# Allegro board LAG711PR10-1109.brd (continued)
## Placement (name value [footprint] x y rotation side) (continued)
RB9  0_0201_5%  [R_0201]  184.1 32.19 180 top
RB10  0_0201_5%  [R_0201]  55.53 26.27 90 top
RB11  0_0201_5%  [R_0201]  169.33 57.26 90 top
RB12  0_0201_5%  [R_0201]  169.33 58.17 270 bottom
RC1  1K_0402_5%  [R_0402]  142.1 81.34 180 bottom
RC2  1K_0402_5%  [R_0402]  139.68 64.07 180 bottom
RC3  49.9_0402_1%  [R_0402]  140.32 80.45 180 bottom
RC4  24.9_0402_1%  [R_0402]  131.49 74.76 180 top
RC5  10K_0402_5%  [R_0402]  109.05 53.27 0 bottom
RC6  10K_0402_5%  [R_0402]  108.67 50.73 0 bottom
RC7  2.2K_0402_5%  [R_0402]  145.27 53.91 180 top
RC8  2.2K_0402_5%  [R_0402]  145.27 53.14 180 top
RC9  2.2K_0402_5%  [R_0402]  140.57 51.37 180 bottom
RC10  100K_0402_5%  [R_0402]  99.83 50.99 180 top
RC11  100K_0402_5%  [R_0402]  131.61 106.1 0 bottom
RC12  100K_0402_5%  [R_0402]  143.75 42.98 180 bottom
RC13  100K_0402_5%  [R_0402]  130.84 51.32 270 top
RC14  0_0201_5%  [R_0201]  108.96 49.97 0 bottom
RC15  49.9_0402_1%  [R_0402]  120.55 59.33 270 top
RC16  49.9_0402_1%  [R_0402]  120.55 56.34 270 top
RC17  121_0402_1%  [R_0402]  119.43 61.91 180 top
RC18  80.6_0402_1%  [R_0402]  120.14 61.91 0 top
RC19  200K_0402_1%  [R_0402]  107.86 110.37 270 top
RC20  100_0402_1%  [R_0402]  117.55 61.81 180 top
RC21  0_0402_5%  [R_0402]  112.81 32.49 90 bottom
RC22  0_0402_5%  [R_0402]  110.52 33.13 90 bottom
RC23  0_0402_5%  [R_0402]  109 33.13 90 bottom
RC24  0_0402_5%  [R_0402]  114.33 33.13 90 bottom
RC25  0_0402_5%  [R_0402]  112.05 33.13 90 bottom
RC26  33_0402_5%  [R_0402]  105.9 53.14 180 top
RC27  10K_0402_5%  [R_0402]  121.07 43.92 90 bottom
RC28  2.2K_0402_5%  [R_0402]  129.19 40.32 90 bottom
RC29  2.2K_0402_5%  [R_0402]  125.13 40.39 270 bottom
RC30  0_0603_5%  [R0603_0OHM]  119.1 39.75 270 bottom
RC31  4.7K_0402_5%  [R_0402]  131.56 37.27 180 bottom
RC32  1K_0402_1%  [R_0402]  108.24 34.04 270 bottom
RC33  1K_0402_5%  [R_0402]  127.16 43.67 90 top
RC34  1K_0402_5%  [R_0402]  127.92 43.67 90 top
RC35  100K_0402_5%  [R_0402]  109.76 33.13 90 bottom
RC36  100K_0402_5%  [R_0402]  115.1 33.13 90 bottom
RC37  100K_0402_5%  [R_0402]  111.29 33.13 90 bottom
RC38  4.7K_0402_5%  [R_0402]  125.76 45.32 90 top
RC39  49.9_0402_1%  [R_0402]  114.72 31.76 270 bottom
RC40  49.9_0402_1%  [R_0402]  113.19 30.84 90 bottom
RC41  49.9_0402_1%  [R_0402]  111.67 31.76 270 bottom
RC42  49.9_0402_1%  [R_0402]  108.37 30.91 90 top
RC43  49.9_0402_1%  [R_0402]  112.18 30.91 90 top
RC44  4.7K_0402_5%  [R_0402]  125 45.32 90 top
RC45  33_0402_5%  [R_0402]  118.19 35.17 0 bottom
RC46  4.7K_0402_5%  [R_0402]  116.49 53.07 90 top
RC47  33_0402_5%  [R_0402]  110.7 62.92 0 bottom
RC48  33_0402_5%  [R_0402]  108.54 60.71 0 bottom
RC49  33_0402_5%  [R_0402]  108.54 62.23 0 bottom
RC50  1K_0402_5%  [R_0402]  110.7 62.16 0 bottom
RC51  4.7K_0402_5%  [R_0402]  108.54 61.47 0 bottom
RC52  10K_0402_5%  [R_0402]  122.72 42.43 270 bottom
RC53  10K_0402_5%  [R_0402]  124.88 43.42 90 top
RC54  200_0402_1%  [R_0402]  116.49 52.21 270 top
RC55  10K_0402_5%  [R_0402]  123.48 41.51 90 bottom
RC56  10K_0402_5%  [R_0402]  125.64 44.33 270 top
RC57  4.7K_0402_5%  [R_0402]  108.67 49.21 0 bottom
RC58  100K_0402_5%  [R_0402]  110.83 57.84 0 bottom
RC59  10K_0402_5%  [R_0402]  119.95 43.92 90 bottom
RC60  150_0201_1%  [R_0201]  117.41 46.45 180 top
RC61  10K_0402_5%  [R_0402]  125.57 52.87 0 top
RC62  4.7K_0402_5%  [R_0402]  119.67 43.92 90 top
RC63  10K_0402_5%  [R_0402]  119.55 42.48 180 bottom
RC64  200_0402_1%  [R_0402]  125.94 48.83 0 top
RC65  4.7K_0402_5%  [R_0402]  119.19 43.92 90 bottom
RC66  10K_0402_5%  [R_0402]  110.83 58.61 0 bottom
RC68  10K_0402_5%  [R_0402]  89.58 117.41 180 top
RC69  10K_0402_5%  [R_0402]  127.16 46.34 90 top
RC70  10K_0402_5%  [R_0402]  130.72 48.62 90 top
RC71  10K_0402_5%  [R_0402]  127.87 48.06 180 top
RC72  10K_0402_5%  [R_0402]  129.96 49.54 270 top
RC73  71.5K_0402_1%  [R_0402]  119.82 50.97 180 top
RC74  75K_0402_1%  [R_0402]  117.26 52.21 270 top
RC75  10K_0402_5%  [R_0402]  96.1 56.07 0 top
RC76  1K_0402_5%  [R_0402]  140.7 71.18 180 bottom
RC77  20K_0402_5%  [R_0402]  103.36 57.4 180 top
RC78  10K_0402_5%  [R_0402]  125.45 116.7 90 bottom
RC79  0_0201_5%  [R_0201]  105.9 56.26 180 top
RC80  0_0201_5%  [R_0201]  105.9 55.49 180 top
RC81  10K_0402_5%  [R_0402]  72.17 136.25 90 top
RC82  20K_0402_5%  [R_0402]  104.99 57.4 0 top
RC83  60.4_0402_1%  [R_0402]  139.66 50.6 0 bottom
RC84  0_0201_5%  [R_0201]  140.84 45.91 0 bottom
RC85  10K_0402_5%  [R_0402]  31.4 81.54 270 top
RC86  10K_0402_5%  [R_0402]  140.8 45.14 0 bottom
RC87  1M_0402_5%  [R_0402]  108.54 59.95 0 bottom
RC88  10K_0402_5%  [R_0402]  29.12 30.11 270 top
RC89  33_0402_5%  [R_0402]  140.17 47.18 0 bottom
RC90  200K_0402_1%  [R_0402]  141.89 47.16 90 bottom
RC91  33_0402_5%  [R_0402]  140.17 48.06 0 bottom
RC92  4.7K_0402_5%  [R_0402]  104.99 54.73 0 top
RC93  10K_0402_5%  [R_0402]  110.83 56.32 0 bottom
RC94  100K_0402_5%  [R_0402]  94.33 54.68 270 top
RC95  10M_0402_5%  [R_0402]  104.16 47.11 0 top
RC96  10K_0402_5%  [R_0402]  110.83 57.08 0 bottom
RC97  10K_0402_5%  [R_0402]  108.54 58.61 0 bottom
RC98  100K_0402_5%  [R_0402]  109.46 57.08 180 bottom
RC99  62_0402_1%  [R_0402]  139.68 64.83 180 bottom
RC100  10K_0402_5%  [R_0402]  131.15 43.8 90 bottom
RC101  0_0201_5%  [R0201_0OHM]  104.99 61.46 0 top
RC102  0_0201_5%  [R0201_0OHM]  104.99 53.97 0 top
RC103  4.7K_0402_5%  [R_0402]  102.45 60.57 0 top
RC104  4.7K_0402_5%  [R_0402]  105.9 60.51 180 top
RC105  1M_0402_5%  [R_0402]  93.84 55.94 180 top
RC106  10K_0402_5%  [R_0402]  104.99 49.33 0 top
RC107  10K_0402_5%  [R_0402]  123.48 44.84 270 bottom
RC108  4.7K_0402_5%  [R_0402]  123.48 43.92 90 top
RC109  10K_0402_5%  [R_0402]  130.08 40.32 90 bottom
RC110  10K_0402_5%  [R_0402]  130.39 43.8 90 bottom
RC111  100K_0402_5%  [R_0402]  122.72 43.92 90 bottom
RC112  4.7K_0402_5%  [R_0402]  119.86 49.2 90 top
RC113  10K_0402_5%  [R_0402]  129.62 43.8 90 bottom
RC114  10K_0402_5%  [R_0402]  121.07 42.43 270 bottom
RC115  4.7K_0402_5%  [R_0402]  110.83 55.56 0 bottom
RC116  150K_0402_5%  [R_0402]  121 39.16 90 bottom
RC117  10K_0402_5%  [R_0402]  121.95 43.92 90 bottom
RC118  10K_0402_5%  [R_0402]  109.46 55.56 180 bottom
RC119  10K_0402_5%  [R_0402]  121.95 42.43 270 bottom
RC120  10K_0402_5%  [R_0402]  120.65 53.78 0 top
RC121  20K_0402_5%  [R_0402]  121.19 43.92 90 top
RC122  20K_0402_5%  [R_0402]  121.95 43.92 90 top
RC123  113_0402_1%  [R_0402]  144.36 54.8 0 top
RC124  0_0402_5%  [R_0402]  131.21 52.97 180 top
RC125  0_0402_5%  [R_0402]  144.36 55.56 0 top
RC126  100_0402_1%  [R_0402]  133.46 51.11 180 top
RC127  10K_0402_5%  [R_0402]  131.81 40.32 180 bottom
RC128  0_0603_5%  [R0603_0OHM]  129.96 59.18 270 top
RC129  0_0603_5%  [R_0603]  145.83 62.16 180 top
RC130  0_0603_5%  [R_0603]  144.37 41.71 180 bottom
RC131  0_0402_5%  [R0402_0OHM]  123.53 60.89 0 top
RC132  0_0402_5%  [R0402_0OHM]  122.5 57.08 90 top
RC133  0_0402_5%  [R_0402]  122.34 55.68 270 top
RC134  56_0402_5%  [R_0402]  142.22 78.54 180 bottom
RC135  220_0402_5%  [R_0402]  139.4 78.54 0 bottom
RC136  100_0402_1%  [R_0402]  140.32 79.56 180 bottom
RC137  1K_0402_1%  [R_0402]  142.74 83.22 180 bottom
RC138  1K_0402_1%  [R_0402]  142.74 83.98 180 bottom
RC139  49.9_0402_1%  [R_0402]  144.29 81.15 0 top
RC140  1K_0402_1%  [R_0402]  140.64 90.99 180 bottom
RC141  1K_0402_1%  [R_0402]  142.27 89.23 180 bottom
RC142  1K_0402_1%  [R_0402]  142.27 87.7 180 bottom
RC143  1K_0402_1%  [R_0402]  142.27 88.46 180 bottom
RC144  10K_0402_1%  [R_0402]  97.65 48.45 180 top
RC145  100K +-5% 0402  [R_0402]  140.5 63.99 90 bottom
RC146  10K_0402_5%  [R_0402]  94.27 46.36 270 top
RC147  0_0201_5%  [R0201_0OHM]  93.21 44.76 0 top
RC148  0_0201_5%  [R0201_0OHM]  93.8 44.13 180 top
RC149  1K_0402_5%  [R_0402]  107.48 33.13 90 bottom
RC150  51_0402_5%  [R_0402]  145.21 84.2 180 top
RC151  51_0402_5%  [R_0402]  145.21 83.43 180 top
RC152  100_0402_5%  [R_0402]  145.21 81.91 180 top
RC153  1.5K_0402_1%  [R_0402]  142.74 82.46 180 bottom
RC154  1.5K_0402_1%  [R_0402]  141.36 86.94 0 bottom
RC155  1K_0402_5%  [R_0402]  103.36 61.53 180 top
RC156  51_0402_5%  [R_0402]  144.29 84.96 0 top
RC157  51_0402_5%  [R_0402]  144.29 82.67 0 top
RC158  10K_0402_5%  [R_0402]  27.09 131.05 90 bottom
RC160  499_0402_1%  [R_0402]  140.32 81.34 180 bottom
RC162  20K_0402_5%  [R_0402]  122.72 43.92 90 top
RC164  100_0402_1%  [R_0402]  144.31 65.07 90 top
RC165  100_0402_1%  [R_0402]  144.31 66.72 90 top
RC167  100_0402_1%  [R_0402]  144.31 71.36 90 top
RC168  100_0402_1%  [R_0402]  144.31 73.01 90 top
RC169  100_0402_1%  [R_0402]  139.86 95.64 270 bottom
RC170  100_0402_1%  [R_0402]  139.86 93.92 270 bottom
RC171  0_0201_5%  [R_0201]  139.7 91.69 0 bottom
RC172  0_0201_5%  [R_0201]  116.49 92.43 270 top
RC173  0_0201_5%  [R_0201]  139.7 92.32 0 bottom
RC174  10K_0402_5%  [R_0402]  128.86 43.8 90 bottom
RC175  10K_0402_5%  [R_0402]  120.43 43.92 90 top
RC177  49.9_0402_1%  [R_0402]  114.21 31.89 270 top
RC178  49.9_0402_1%  [R_0402]  112.43 30.84 90 bottom
RC179  49.9_0402_1%  [R_0402]  111.41 30.91 90 top
RC180  49.9_0402_1%  [R_0402]  109.13 30.91 90 top
RC181  49.9_0402_1%  [R_0402]  110.91 31.76 270 bottom
RC182  4.7K_0402_5%  [R_0402]  117.78 48.69 270 top
RC183  4.7K_0402_5%  [R_0402]  118.54 48.69 270 top
RC187  100K_0402_5%  [R_0402]  113.57 33.13 90 bottom
RC188  10K_0402_5%  [R_0402]  131.48 49.54 270 top
RC189  10K_0402_5%  [R_0402]  133 49.54 270 top
RC190  10K_0402_5%  [R_0402]  133.77 49.54 270 top
RC191  10K_0402_5%  [R_0402]  132.24 49.54 270 top
RC192  15_0402_5%  [R_0402]  105.9 50.1 180 top
RC193  15_0402_5%  [R_0402]  105.9 50.86 180 top
RC194  15_0402_5%  [R_0402]  105.9 51.62 180 top
RC195  15_0402_5%  [R_0402]  105.9 52.38 180 top
RC196  1K_0402_5%  [R_0402]  127.34 43.29 90 bottom
RC197  1K_0402_5%  [R_0402]  128.1 43.29 90 bottom
RC198  1K_0402_5%  [R_0402]  130.03 39.56 180 bottom
RC199  1K_0402_5%  [R_0402]  128.89 42.1 180 bottom
RC200  10K_0402_5%  [R_0402]  125 43.92 90 bottom
RC201  10K_0402_5%  [R_0402]  124.24 44.84 270 bottom
RC202  20K_0402_5%  [R_0402]  123.1 51.44 270 top
RC203  10K_0402_5%  [R_0402]  145.21 50.41 180 top
RC204  10K_0402_5%  [R_0402]  208.66 55.33 270 top
RC205  100K_0402_5%  [R_0402]  121.56 54.61 180 top
RC206  10K_0402_5%  [R_0402]  190.61 38.54 180 bottom
RC207  4.7K_0402_5%  [R_0402]  131.09 36.09 270 bottom
RC208  10K_0402_5%  [R_0402]  118.16 49.42 0 top
RC209  10K_0402_5%  [R_0402]  119.07 50.19 180 top
RD1  240_0402_1%  [R_0402]  71.96 76.62 180 top
RD2  0_0201_5%  [R_0201]  69.63 42.95 90 top
RD3  0_0201_5%  [R0201_0OHM]  69.63 44.79 90 top
RD4  0_0201_5%  [R_0201]  68.93 42.95 90 top
RD5  0_0201_5%  [R0201_0OHM]  68.93 44.79 90 top
RD6  0_0201_5%  [R_0201]  68.87 68.11 270 top
RD7  0_0201_5%  [R0201_0OHM]  68.21 67.5 180 top
RD8  470_0402_1%  [R_0402]  70.85 82.86 180 top
RD9  0_0201_5%  [R0201_0OHM]  68.51 82.86 0 top
RD10  1K_0402_1%~D  [R_0402]  70.78 67.48 0 top
RD11  2_0402_1%  [R_0402]  70.78 64.62 0 top
RD12  1K_0402_1%~D  [R_0402]  71.7 66.53 180 top
RD13  24.9_0402_1%  [R_0402]  71.67 62.67 180 top
RD14  240_0402_1%  [R_0402]  59.04 77.15 180 top
RD15  0_0201_5%  [R_0201]  55.75 44.76 0 top
RD16  0_0201_5%  [R0201_0OHM]  57.65 44.76 0 top
RD17  0_0201_5%  [R0201_0OHM]  55.75 44.13 0 top
RD18  0_0201_5%  [R_0201]  57.65 44.13 0 top
RD19  0_0201_5%  [R_0201]  56.3 67.79 270 top
RD20  0_0201_5%  [R0201_0OHM]  56.3 66.52 270 top
RD21  1K_0402_1%~D  [R_0402]  58.12 67.88 0 top
RD22  2_0402_1%  [R_0402]  58.12 66.99 0 top
RD23  1K_0402_1%~D  [R_0402]  59.04 68.77 180 top
RD24  24.9_0402_1%  [R_0402]  59.04 65.21 180 top
RE1  100K_0402_1%  [R_0402]  35.64 92.01 0 top
RE2  100K_0402_1%  [R_0402]  34.88 91.12 0 top
RE3  100K_0402_1%  [R_0402]  30.95 87.24 270 top
RE4  100K_0402_1%  [R_0402]  31.72 87.23 270 top
RE5  0_0603_5%  [R0603_0OHM]  53.63 87.12 270 top
RE6  0_0603_5%  [R0603_0OHM]  30.06 66.29 270 top
RE7  0_0603_5%  [R_0603]  55.34 77.02 180 top
RE8  4.7K_0402_5%  [R_0402]  39.91 64.52 270 top
RE9  4.7K_0402_5%  [R_0402]  40.67 64.52 270 top
RE10  2.2K_0402_5%  [R_0402]  41.44 64.52 270 top
RE11  2.2K_0402_5%  [R_0402]  42.2 64.52 270 top
RE12  100K_0402_5%  [R_0402]  53.04 67.75 0 top
RE16  10K_0402_5%  [R_0402]  53.51 72.69 0 top
RE17  10K_0402_5%  [R_0402]  55.89 74.4 0 top
RE18  100K_0402_5%  [R_0402]  48.95 86.46 90 top
RE19  100K_0402_5%  [R_0402]  42.96 65.41 270 top
RE20  100K_0402_5%  [R_0402]  31.4 66 0 top
RE21  100K_0402_5%  [R_0402]  29.51 86.7 180 top
RE22  10K_0402_5%  [R_0402]  131.91 44.71 270 bottom
RE23  100K_0402_5%  [R_0402]  37.68 64.52 270 top
RE24  10K_0402_5%  [R_0402]  50.85 86.26 90 top
RE25  100_0402_5%  [R_0402]  32.32 65.21 180 top
RE26  10K_0402_5%  [R_0402]  49.18 65.41 270 top
RE27  43_0402_1%  [R_0402]  37.63 85.96 90 top
RE28  100K_0402_5%  [R_0402]  52.58 87.11 270 top
RE29  0_0201_5%  [R0201_0OHM]  29.63 73.12 270 top
RE30  1K_0402_5%  [R_0402]  32.09 73.67 180 top
RE31  100K_0402_5%  [R_0402]  32.32 66.78 180 top
RE32  100K_0402_5%  [R_0402]  32.09 72.75 180 top
RE34  0_0201_5%  [R0201_0OHM]  51.3 63.81 0 top
RE35  10K_0402_1%  [R_0402]  46.52 65.41 270 top
RE36  100K_0402_5%  [R_0402]  52.18 65.46 180 top
RE38  100K_0402_5%  [R_0402]  51.27 64.57 0 top
RE39  33_0402_5%  [R_0402]  54.85 80.07 180 top
RE40  10K_0402_1%  [R_0402]  48.42 65.41 270 top
RE41  0_0201_5%  [R0201_0OHM]  54.17 75.05 180 top
RE42  0_0402_5%  [R_0402]  33.09 68.95 270 top
RE43  0_0402_5%  [R0402_0OHM]  33.09 70.73 270 top
RE44  0_0603_5%  [R0603_0OHM]  33.78 89.64 90 top
RE45  100K_0402_5%  [R_0402]  37.12 88.88 90 top
RE46  300_0402_5%  [R_0402]  30.2 77.14 90 top
RE47  300_0402_5%  [R_0402]  32.09 74.46 180 top
RE48  49.9_0402_1%  [R_0402]  45.06 94.03 90 top
RE49  10K_0402_5%  [R_0402]  41.25 94.03 90 top
RE50  100K_0402_5%  [R_0402]  40.48 94.03 90 top
RE51  10K_0402_5%  [R_0402]  38.83 94.03 90 top
RE52  10K_0402_5%  [R_0402]  38.07 94.03 90 top
RE53  0_0201_5%  [R0201_0OHM]  33.14 81.78 0 top
RE54  0_0201_5%  [R0201_0OHM]  40.8 86.84 270 top
RE55  0_0201_5%  [R0201_0OHM]  33.14 81.15 0 top
RE57  10K_0402_5%  [R_0402]  39.72 94.94 270 top
RE58  100K_0402_5%  [R_0402]  39.53 86.88 270 top
RE60  100K_0402_5%  [R_0402]  46.31 93.4 0 top
RE65  0_0201_5%  [R_0201]  46.87 97.91 180 top
RE66  10K_0201_5%  [R_0201]  33.37 83.17 270 top
RE67  10K_0201_5%  [R_0201]  32.77 83.17 270 top
RE68  10K_0201_5%  [R_0201]  38.52 63.9 90 top
RE69  10K_0201_5%  [R_0201]  39.15 63.9 90 top
RE70  10K_0201_5%  [R_0201]  32.13 76.92 0 top
RE71  10K_0201_5%  [R_0201]  32.13 77.55 0 top
RE72  10K_0201_5%  [R_0201]  32.13 78.19 0 top
RE73  10K_0201_5%  [R_0201]  32.13 78.82 0 top
RE74  100K_0201_5%  [R_0201]  44.48 61.36 90 top
RE75  100K_0201_5%  [R_0201]  45.12 61.36 90 top
RE76  100K_0201_5%  [R_0201]  45.75 61.36 90 top
RE77  100K_0201_5%  [R_0201]  46.39 61.36 90 top
RE78  100K_0201_5%  [R_0201]  54.8 68.94 180 top
RE79  100K_0201_5%  [R_0201]  54.8 69.58 180 top
RE80  100K_0201_5%  [R_0201]  54.2 70.73 180 top
RE81  100K_0201_5%  [R_0201]  54.17 75.62 180 top
RE82  100K_0201_5%  [R_0201]  47.79 87.3 270 top
RE83  100K_0201_5%  [R_0201]  47.15 87.3 270 top
RE84  100K_0201_5%  [R_0201]  46.52 87.3 270 top
RE85  100K_0201_5%  [R_0201]  45.88 87.3 270 top
RE86  100K_0201_5%  [R_0201]  54.17 74.35 180 top
RE87  100K_0201_5%  [R_0201]  41.44 86.84 270 top
RE88  100K_0201_5%  [R_0201]  45.25 87.3 270 top
RE89  100K_0201_5%  [R_0201]  38.77 86.84 270 top
RE90  10K_0402_5%  [R_0402]  44.29 94.03 90 top
RE91  10K_0402_5%  [R_0402]  43.53 94.03 90 top
RE92  10K_0402_5%  [R_0402]  42.77 94.03 90 top
RE93  10K_0402_5%  [R_0402]  42.01 94.03 90 top
RE94  10K_0402_5%  [R_0402]  34.13 73.83 90 top
RE95  0_0402_5%  [R_0402]  48.8 93.33 90 top
RH1  100K_0402_1%_B25/50 4250K  [R_0402]  128.69 44.59 270 top
RI1  5.6_0402_1%  [R_0402]  17.24 93.64 180 top
RI2  5.6_0402_1%  [R_0402]  17.24 96.69 180 top
RI3  150_0402_5%  [R_0402]  14.92 94.48 270 top
RI4  150_0402_5%  [R_0402]  14.92 96.57 270 top
RI5  5.6_0402_1%  [R_0402]  17.24 94.66 180 top
RI6  5.6_0402_1%  [R_0402]  17.24 95.67 180 top
RI7  5.6_0402_1%  [R_0402]  17.24 89.7 180 top
RI8  5.6_0402_1%  [R_0402]  17.24 91.67 180 top
RI9  150_0402_5%  [R_0402]  14.92 90.54 270 top
RI10  150_0402_5%  [R_0402]  14.92 92.64 270 top
RI11  5.6_0402_1%  [R_0402]  17.24 90.72 180 top
RI12  5.6_0402_1%  [R_0402]  17.24 92.69 180 top
RI13  1M_0402_5%  [R_0402]  12.66 112.45 0 bottom
RI14  2.2K_0402_5%  [R_0402]  26.4 90.29 180 bottom
RI15  2.2K_0402_5%  [R_0402]  20.79 88.45 0 bottom
RI16  20K_0402_5%  [R_0402]  13.04 108.26 0 bottom
RI17  470_0402_5%  [R_0402]  19.01 92.51 0 bottom
RI18  470_0402_5%  [R_0402]  19.01 91.75 0 bottom
RI19  470_0402_5%  [R_0402]  19.01 90.61 0 bottom
RI20  470_0402_5%  [R_0402]  19.01 89.85 0 bottom
RI21  470_0402_5%  [R_0402]  19.21 96.45 0 bottom
RI22  470_0402_5%  [R_0402]  19.21 95.69 0 bottom
RI23  470_0402_5%  [R_0402]  19.21 94.55 0 bottom
RI24  470_0402_5%  [R_0402]  19.21 93.78 0 bottom
RL1  0_0603_5%  [R_0603]  21.59 85.64 90 top
RL2  33_0402_5%  [R_0402]  19.04 82.29 0 top
RL3  33_0402_5%  [R_0402]  20 80.58 90 top
RL4  0_0603_5%  [R0603_0OHM]  20.9 85.01 0 bottom
RL5  0_0201_5%  [R0201_0OHM]  30.43 80.64 180 top
RL6  10K_0402_5%  [R_0402]  20.68 79.62 180 bottom
RL7  2.49K_0402_1%~D  [R_0402]  19.74 79.76 0 top
RL8  1K_0402_5%  [R_0402]  24.6 87.22 270 top
RL9  15K_0402_1%  [R_0402]  24.62 88.01 180 top
RL10  10K_0402_5%  [R_0402]  22.2 88.72 180 top
RL11  100K_0402_5%  [R_0402]  15.82 88.67 270 top
RL12  75_0603_5%  [R_0603]  18.58 77.15 270 top
RL13  75_0603_5%  [R_0603]  19.85 77.15 270 top
RL14  75_0603_5%  [R_0603]  18.58 77.15 270 bottom
RL15  75_0603_5%  [R_0603]  19.85 77.15 270 bottom
RL16  0_0201_5%  [R_0201]  17.15 79.43 180 top
RO1  10K_0402_5%  [R_0402]  191.3 62.49 270 bottom
RP34  10K_0804_8P4R_5%  [RP_0804_8P4R]  128.36 115.05 90 bottom
RS1  10K_0402_5%  [R_0402]  24.74 36.47 180 bottom
RS2  0_0201_5%  [R_0201]  39.87 24.32 0 bottom
RS3  0_0603_5%  [R_0603]  26.58 30.09 270 top
RS28  0_0201_5%  [R_0201]  188.16 37.4 180 bottom
RS29  0_0201_5%  [R_0201]  168.14 29.78 0 top
RS30  100K_0402_5%  [R_0402]  169.27 31.45 90 top
RS31  100K_0402_5%  [R_0402]  165.26 31.76 270 top
RS32  0_1206_5%  [R_1206]  181.2 34.22 0 top
RS33  0_0201_5%  [R_0201]  189.68 37.78 180 bottom
RS34  0_0201_5%  [R0201_0OHM]  33.1 33.83 0 top
RT1  0_0603_5%  [R_0603]  29.05 112.52 90 bottom
RT2  10K_0402_5%  [R_0402]  25.23 116.52 0 bottom
RT3  100K_0402_1%  [R_0402]  25.23 117.28 0 bottom
RT4  100K_0402_1%  [R_0402]  25.23 118.3 0 bottom
RT5  0_0201_5%  [R_0201]  33.7 115.5 0 bottom
RT6  100K_0402_5%  [R_0402]  33.87 116.26 0 bottom
RT7  100K_0402_5%  [R_0402]  33.87 119.31 0 bottom
RT8  100K_0402_5%  [R_0402]  33.87 118.55 0 bottom
RT9  100K_0402_5%  [R_0402]  26.15 115.5 180 bottom
RT10  100K_0402_5%  [R_0402]  33.87 117.79 0 bottom
RT11  100K_0402_5%  [R_0402]  33.87 117.03 0 bottom
RT12  47K_0402_5%  [R_0402]  25.43 117.61 270 top
RT13  4.7K_0402_5%  [R_0402]  24.48 126.44 270 top
RT14  4.7K_0402_5%  [R_0402]  20.61 126.18 270 top
RT15  4.7K_0402_5%  [R_0402]  25.43 118.98 90 top
RT16  4.7K_0402_5%  [R_0402]  20.99 118.98 90 top
RT17  4.7K_0402_5%  [R_0402]  23.66 126.44 270 top
RT18  4.7K_0402_5%  [R_0402]  21.43 126.18 270 top
RT19  4.7K_0402_5%  [R_0402]  24.55 118.98 90 top
RT20  4.7K_0402_5%  [R_0402]  21.88 118.98 90 top
RT21  0_0402_5%  [R_0402-NPM]  18.02 119.18 180 top
RT22  0_0402_5%  [R_0402-NPM]  18.02 119.95 180 top
RT23  100K_0402_5%  [R_0402]  19.58 115.31 0 top
RU1  0_0402_5%  [R_0402-NPM]  26.65 55.81 180 top
RU2  0_0402_5%  [R_0402-NPM]  26.65 55.05 180 top
RU3  0_0402_5%  [R_0402]  22.47 59.8 0 top
RU4  0_0402_5%  [R_0402]  22.47 57.95 0 top
RU5  0_0402_5%  [R_0402]  22.47 58.78 0 top
RU6  0_0402_5%  [R_0402]  22.47 56.94 0 top
RU7  0_0402_5%  [R_0402-NPM]  32.15 39.41 180 bottom
RU8  0_0402_5%  [R_0402-NPM]  32.15 40.17 180 bottom
RU9  0_0402_5%  [R_0402]  20.88 33.07 0 top
RU10  0_0402_5%  [R_0402]  21 31.05 0 top
RU11  0_0402_5%  [R_0402]  20.88 32.31 0 top
RU12  0_0402_5%  [R_0402]  21 30.29 0 top
RU13  0_0402_5%  [R_0402-NPM]  210.9 33.61 90 top
RU14  0_0402_5%  [R_0402-NPM]  210.14 33.61 90 top
RU15  0_0402_5%  [R_0402-NPM]  208.57 37.09 270 top
RU16  0_0402_5%  [R_0402-NPM]  207.81 37.09 270 top
RV1  1.69K_0402_1%  [R_0402]  121.25 139.12 90 top
RV2  1K_0402_1%  [R_0402]  124.14 128.39 0 top
RV3  1K_0402_1%  [R_0402]  120.17 139.12 90 top
RV4  100K_0402_5%  [R_0402]  110.22 138.11 180 bottom
RV5  4.7K_0402_5%  [R_0402]  123.95 123.53 0 top
RV6  4.7K_0402_5%  [R_0402]  122.66 119.67 90 top
RV7  0_0603_5%  [R0603_0OHM]  110.16 136.09 45 top
RV8  8.45K_0402_1%  [R_0402]  115.68 134.27 90 top
RV9  2K_0402_1%  [R_0402]  116.58 135.17 270 top
RV10  0_0603_5%  [R0603_0OHM]  109.19 135.19 0 bottom
RV11  8.45K_0402_1%  [R_0402]  113.89 136.61 270 top
RV12  2K_0402_1%  [R_0402]  114.78 135.71 90 top
RV13  8.45K_0402_1%  [R_0402]  112.81 134.81 270 top
RV14  4.75K_0402_1%  [R_0402]  113.89 133.91 90 top
RV15  8.45K_0402_1%  [R_0402]  113.32 138.88 270 top
RV16  4.75K_0402_1%  [R_0402]  114.08 137.97 90 top
RV17  5.1K_0402_1%  [R_0402]  127.36 121.15 90 top
RV18  1K_0402_1%  [R_0402]  128.18 121.15 90 top
RV19  10K_0402_5%  [R_0402]  127.99 119.71 270 top
RV20  1M_0402_5%  [R_0402]  109.64 142.25 270 bottom
RV21  10K_0402_5%  [R_0402]  123.92 118.47 90 bottom
RV22  10K_0402_5%  [R_0402]  123.16 118.6 90 bottom
RV23  0_0603_5%  [R0603_0OHM]  122.34 140.46 270 top
RV24  0_0603_5%  [R_0603]  118.4 123.69 0 top
RV25  0_0402_5%  [R_0402]  109.64 123.93 90 bottom
RV26  0_0402_5%  [R_0402]  108.81 124.85 270 bottom
RV27  0_0603_5%  [R0603_0OHM]  111.51 129.36 0 top
RV29  10K_0402_5%  [R_0402]  118.33 139.64 270 top
RV30  0_0603_5%  [R0603_0OHM]  112.24 128.13 0 top
RV31  0_0603_5%  [R0603_0OHM]  120.29 143.27 0 top
RV32  40.2_0402_1%  [R_0402]  132.42 147.38 0 bottom
RV33  40.2_0402_1%  [R_0402]  131.43 146.36 180 bottom
RV34  100_0402_1%  [R_0402]  130.51 147.13 0 bottom
RV35  100_0402_1%  [R_0402]  134.64 147.38 0 bottom
RV36  49.9_0402_1%  [R_0402]  150.05 116.58 270 bottom
RV37  10_0402_1%  [R_0402]  149.29 116.58 270 bottom
RV38  5.1K_0402_1%  [R_0402]  148.53 116.58 270 bottom
RV39  120_0402_1%  [R_0402]  124.86 143.12 0 top
RV40  51.1_0402_1%  [R_0402]  129.76 119.17 90 top
RV41  51.1_0402_1%  [R_0402]  128.32 123.82 180 top
RV42  10_0402_5%  [R_0402]  118.96 137.66 0 top
RV43  10_0402_5%  [R_0402]  99.54 119.39 270 top
RV44  0_0402_5%  [R_0402]  124.68 118.47 90 bottom
RV45  0_0402_5%  [R_0402]  122.27 118.6 90 bottom
RV48  2.37K_0402_1%  [R_0402]  160.36 123.76 0 top
RV49  5.49K_0402_1%  [R_0402]  161.27 124.65 180 top
RV50  2.37K_0402_1%  [R_0402]  157 132.92 270 bottom
RV51  5.49K_0402_1%  [R_0402]  155.22 132.01 90 bottom
RV52  2.37K_0402_1%  [R_0402]  164.06 146.24 270 top
RV53  5.49K_0402_1%  [R_0402]  163.98 143.5 0 top
RV54  2.37K_0402_1%  [R_0402]  153.62 149.06 90 bottom
RV55  5.49K_0402_1%  [R_0402]  154.64 149.92 0 bottom
RV59  10K_0402_5%  [R_0402]  119.18 140.03 270 top
RV78  60.4_0402_1%  [R_0402]  154.64 149.96 270 top
RV79  60.4_0402_1%  [R_0402]  155.53 149.96 270 top
RV80  4.7K_0402_5%  [R_0402]  126.02 120.66 270 top
RV81  4.7K_0402_5%  [R_0402]  120.62 119.52 270 bottom
RV82  4.7K_0402_5%  [R_0402]  121.38 119.52 270 bottom
RV83  16.2K_0402_1%  [R_0402]  119.86 119.52 270 bottom
RV84  10K_0402_5%  [R_0402]  108.96 127.11 180 bottom
RV85  60.4_0402_1%  [R_0402]  155.3 132.93 270 top
RV86  60.4_0402_1%  [R_0402]  156.12 132.93 270 top
RV87  10K_0402_5%  [R_0402]  108.94 128.01 180 bottom
RV88  10K_0402_5%  [R_0402]  108.02 128.91 0 bottom
RV89  10K_0402_5%  [R_0402]  110.74 128.33 180 bottom
RV117  1K_0402_1%  [R_0402]  153.64 116.65 270 bottom
RV119  1K_0402_1%  [R_0402]  164.11 123.63 0 bottom
RV121  121_0402_1%  [R_0402]  158.45 132.01 90 bottom
RV123  121_0402_1%  [R_0402]  156.4 149 90 bottom
RV134  1K_0402_1%  [R_0402]  155.38 133.97 0 bottom
RV135  1K_0402_1%  [R_0402]  163.98 142.55 0 top
RV151  10K_0402_5%  [R_0402]  126.97 119.52 270 bottom
RV152  10K_0402_5%  [R_0402]  126.21 118.6 90 bottom
RV153  0_0402_5%  [R_0402]  125.45 118.6 90 bottom
RV155  0_0402_5%  [R_0402]  110.74 130.1 180 bottom
RV156  0_0402_5%  [R_0402]  110.74 129.23 180 bottom
RV157  0_0402_5%  [R_0402]  110.74 127.49 180 bottom
RV158  0_0402_5%  [R_0402]  116.31 138.34 90 top
RV159  0_0402_5%  [R_0402]  117.21 138.34 90 top
RV162  4.7K_0402_5%  [R_0402]  109.3 136.33 0 bottom
RV163  4.7K_0402_5%  [R_0402]  110.22 137.22 180 bottom
RV165  10K_0402_1%  [R_0402]  58.96 126.12 270 top
RV166  8.2K_0402_5%  [R_0402]  59.85 125.2 90 top
RW1  0_0603_5%  [R_0603]  67.92 139.38 0 top
RW2  0_0603_5%  [R_0603]  66.58 117.15 0 top
RW3  22_0402_5%  [R_0402]  63.86 126.04 180 top
RW4  0_0402_5%  [R_0402]  63.86 126.93 180 top
RW5  75_0402_5%  [R_0402]  105.24 42.35 0 top
RW6  22_0402_5%  [R_0402]  63.86 128.71 180 top
RW7  75_0402_5%  [R_0402]  105.24 41.46 0 top
RW8  0_0201_5%  [R0201_0OHM]  73.57 137.21 270 top
RW10  0_0201_5%  [R_0201]  74.2 137.21 270 top
RX1  10K_0402_5%  [R_0402]  82.99 37.54 180 top
RX5  49.9_0402_1%  [R_0402]  110.65 31.82 270 top
RX6  49.9_0402_1%  [R_0402]  109.89 31.82 270 top
RX9  49.9_0402_1%  [R_0402]  113.95 31.76 270 bottom
RX10  0_0402_5%  [R0402_0OHM]  91.64 33.19 0 top
RX11  0_0402_5%  [R_0402]  92.55 34.11 180 top
RX12  0_0402_5%  [R_0402]  91.42 37.99 0 top
RX13  0_0402_5%  [R_0402]  84.54 40.25 0 top
RX14  0_0402_5%  [R_0402]  82.51 33.65 180 top
RX15  0_0402_5%  [R_0402]  81.97 36.15 0 top
RX16  0_0402_5%  [R_0402]  79.83 34.49 90 top
RX17  0_0402_5%  [R_0402]  85.45 41.91 180 top
RX18  0_0402_5%  [R_0402]  92.55 32.37 180 top
RX19  0_0402_5%  [R_0402]  93.38 32.27 90 top
RX20  0_0402_5%  [R_0402]  85.45 41.07 180 top
RX21  0_0402_5%  [R_0402]  89.05 39.56 0 top
RX22  0_0402_5%  [R_0402]  89.76 31.68 180 top
RZ1  0 +-1% 0402  [R_0402]  131.17 107.88 180 bottom
RZ2  0_0201_5%  [R_0201]  94.4 51.29 90 top
RZ3  49.9K_0402_1%  [R_0402]  154.97 41.13 90 top
RZ4  0_0402_5%  [R_0402]  71.99 30.23 180 top
RZ5  0_0402_5%  [R_0402]  137.71 115.11 180 bottom
RZ6  10K_0402_5%  [R_0402]  120.56 106.66 90 bottom
RZ7  10K_0402_5%  [R_0402]  117 106.66 90 bottom
RZ8  0_0201_5%  [R0201_0OHM]  71.37 29.52 0 top
RZ9  0_0201_5%  [R_0201]  72.08 109.28 180 top
RZ10  0_0402_5%  [R_0402]  93.89 58.28 90 top
RZ11  0_0402_5%  [R_0402]  104.81 65.41 270 top
RZ12  0_0402_5%  [R_0402]  99.02 61.4 0 top
SW1  TST71-N-220-T170-S017_2P  [SW_TST71-N-220-T170-S017_2P]  31.22 62.29 180 top
TL1  NS681611H LAN  [BOTH_NS0014-LF_16P]  16.98 73.13 270 top
TL2  NS681611H LAN  [BOTH_NS0014-LF_16P]  16.98 64.24 90 bottom
TP1  PAD  [TPC12]  133.71 73.07 0 top
TP2  PAD  [TPC12]  139.49 83.71 180 bottom
TP3  PAD  [TPC12]  138.18 83.79 180 bottom
TP4  PAD  [TPC12]  140.81 83.73 180 bottom
TP5  PAD  [TPC12]  134.02 84.13 0 top
TP6  PAD  [TPC12]  130.34 54.01 0 top
TP7  PAD  [TPC12]  140.93 82.35 180 bottom
TP8  PAD  [TPC12]  139.62 82.32 180 bottom
TP9  PAD  [TPC12]  109.7 85.34 180 bottom
TP10  PAD  [TPC12]  120.33 82.88 0 top
TP11  PAD  [TPC12]  110.84 84.2 180 bottom
TP12  PAD  [TPC12]  118.91 83.94 0 top
TP14  PAD  [TPC12]  138.59 70.16 180 bottom
TP15  PAD  [TPC12]  139.9 70.16 180 bottom
TP16  PAD  [TPC12]  108.62 63.43 180 bottom
TP17  PAD  [TPC12]  93.18 50.53 0 top
TP18  PAD  [TPC12]  124.84 95.75 0 top
TP19  PAD  [TPC12]  119.54 58.48 0 top
TP20  PAD  [TPC12]  141.64 71.18 180 bottom
TP21  PAD  [TPC12]  116.92 58.39 0 top
TP22  PAD  [TPC12]  118.23 58.45 0 top
TP23  PAD  [TPC12]  103.03 56.32 0 top
TP24  PAD  [TPC12]  110.97 52.12 180 bottom
TP25  PAD  [TPC12]  108.85 54.24 180 bottom
TP26  PAD  [TPC12]  129.07 53.53 0 top
TP27  PAD  [TPC12]  127.8 54.02 0 top
TP28  PAD  [TPC12]  110.23 54.58 180 bottom
TP29  PAD  [TPC12]  111.54 54.62 180 bottom
TP30  PAD  [TPC12]  119.64 60.3 0 top
TP31  PAD  [TPC12]  118.33 60.27 0 top
TP32  PAD  [TPC12]  111.87 44.45 180 bottom
TP34  PAD  [TPC12]  113.45 44.41 180 bottom
TP46  PAD  [TPC12]  73.44 66.89 0 top
TP47  PAD  [TPC12]  79.66 66.86 0 top
TP48  PAD  [TPC12]  57.18 67.16 0 top
TP49  PAD  [TPC12]  65.16 66.81 0 top
TP51  PAD  [TPC12]  68.61 117.66 180 bottom
TP52  PAD  [TPC12]  66.96 117.79 180 bottom
TP53  PAD  [TPC12]  20.9 82.47 0 top
TP54  PAD  [TPC12]  19.76 84.62 0 top
TP55  PAD  [TPC12]  200.19 64.45 180 bottom
TP56  PAD  [TPC12]  125.36 127.31 0 top
TP57  PAD  [TPC12]  127.85 127.36 0 top
TP58  PAD  [TPC12]  117.05 127.17 0 top
TP59  PAD  [TPC12]  121.81 127.77 0 top
TP60  PAD  [TPC12]  116.87 125.89 0 top
TP61  PAD  [TPC12]  116.85 128.48 0 top
TP62  PAD  [TPC12]  119.6 128.06 0 top
TP63  PAD  [TPC12]  117.7 124.9 0 top
TP64  PAD  [TPC12]  118.51 127.36 0 top
TP65  PAD  [TPC12]  118.5 125.95 0 top
TP66  PAD  [TPC12]  119.62 126.6 0 top
TP67  PAD  [TPC12]  119.57 125.24 0 top
TP68  PAD  [TPC12]  120.9 126.36 0 top
TP69  PAD  [TPC12]  117 120.45 180 bottom
TP70  PAD  [TPC12]  118.32 120.48 180 bottom
TP71  PAD  [TPC12]  122.2 124.99 0 top
TP72  PAD  [TPC12]  120.9 125 0 top
TP73  PAD  [TPC12]  121.07 120.52 180 bottom
TP74  PAD  [TPC12]  118.61 119.16 180 bottom
TP75  PAD  [TPC12]  123.64 120.58 180 bottom
TP76  PAD  [TPC12]  123.86 124.98 0 top
TP77  PAD  [TPC12]  121.78 123.02 0 top
TP78  PAD  [TPC12]  112.92 126.63 0 top
TP79  PAD  [TPC12]  119.08 132.6 0 top
TP80  PAD  [TPC12]  91.27 35.2 0 top
TP81  PAD  [TPC12]  92.57 35.21 0 top
TPC1  PAD  [TPC12]  133.04 81.4 0 top
TPC2  PAD  [TPC12]  132.53 85.1 0 top
TPC3  PAD  [TPC12]  134.72 82.52 0 top
TPC4  PAD  [TPC12]  135 85.62 0 top
TPC5  PAD  [TPC12]  132.46 83.23 0 top
TPC6  PAD  [TPC12]  134.44 80.35 0 top
TPC7  PAD  [TPC12]  138.32 82.37 180 bottom
TPC8  PAD  [TPC12]  106.08 34.09 180 bottom
TPC9  PAD  [TPC12]  143.24 89.71 180 bottom
TPC10  PAD  [TPC12]  101.38 61.53 0 top
TPC11  PAD  [TPC12]  138.59 85 180 bottom
TPC12  PAD  [TPC12]  141.89 85.33 180 bottom
TPC13  PAD  [TPC12]  143.06 86.03 180 bottom
TPC14  PAD  [TPC12]  138.29 86.71 180 bottom
TPC15  PAD  [TPC12]  139.89 84.96 180 bottom
TPC16  PAD  [TPC12]  140.31 87.21 180 bottom
TPC17  PAD  [TPC12]  141.64 90.69 180 bottom
TPC18  PAD  [TPC12]  140.41 88.49 180 bottom
TPC19  PAD  [TPC12]  140.52 90.04 180 bottom
TPC20  PAD  [TPC12]  139.1 87.77 180 bottom
TPC21  PAD  [TPC12]  139.43 89.35 180 bottom
TPC22  PAD  [TPC12]  139.47 86.2 180 bottom
TPC23  PAD  [TPC12]  138.27 88.77 180 bottom
TPC24  PAD  [TPC12]  140.79 86.03 180 bottom
U1  -  [SY6288C20AAC_SOT23-5]  217.66 58.03 270 top
U2  -  [SY6288C20AAC_SOT23-5]  213.92 37.5 180 top
U3  -  [NCT7718W_MSOP8]  181.08 62.85 225 bottom
UA1  -  [ALC3204-CG_MQFN40_5X5]  34.21 11.21 180 top
UC1  WHL-U42_BGA1528  [WHL-U42_BGA_1528P-T]  136.55 92.62 180 bottom
UC2  -  [74AUP1G07GW_TSSOP5]  105.81 106.22 0 top
UC3  W25Q128JVSIQ_SO8  [W25Q128FVSIQ_SO8]  128.5 37.4 270 bottom
UC4  -  [SN74AHC1G08DCKR_SC70-5]  97.7 53.64 90 top
UC5  -  [SN74AHC1G08DCKR_SC70-5]  95.66 58.49 270 top
UC6  -  [74AUP1G07GW_TSSOP5]  97.3 38.53 0 top
UC8  -  [74AUP1G07GW_TSSOP5]  95.4 44.4 270 top
UC9  -  [SN74AHC1G08DCKR_SC70-5]  97.7 50.97 90 top
UC11  W25Q128JVSIQ_SO8  [W25Q128FVSIQ_SO8]  132.24 33.02 0 bottom
UE1  -  [MEC1416-NU-D0_VTQFP128_14X14]  37.35 67.78 90 top
UE2  -  [NL17SZ06DFT2G_SC70-5]  38.07 90.5 270 top
UL1  RTL8106E-CG_QFN32_4X4  [RTL8106E-CG_QFN32_4X4-S]  22.8 80.19 0 top
UL2  -  [SY6288C20AAC_SOT23-5]  19.29 86.66 90 top
US2  -  [LNG2DMTR_LGA12_2X2]  170.23 28.85 90 top
UT1  TPS25810RVCR_QFN20_4X3  [TPS25810RVCR_QFN20_4X3-S]  31 115.86 180 bottom
UT2  -  [TUSB542RWQR_X2QFN18_2X2P4]  23.24 124.01 270 top
UU1  -  [SY6288D20AAC_SOT23-5]  19.02 52.57 0 bottom
UU2  -  [SY6288D20AAC_SOT23-5]  203.64 32.68 270 top
UV1  216-0842024-A11-MAR_FCBGA631  [216-0842024-A11-MAR_FCBGA_631P]  134.54 122.6 90 bottom
UV2  MC74VHC1G08DFT2G_SC70-5  [SN74AHC1G08DCKR_SC70-5]  109.4 120.26 180 bottom
UV3  MC74VHC1G08DFT2G_SC70-5  [SN74AHC1G08DCKR_SC70-5]  63.16 123.49 90 top
UV13  H5GC4H24AJR-R0C_BGA170  [H5GC4H24AJR-R0C_BGA_170P]  161.51 136.33 90 bottom
UV15  H5GC4H24AJR-R0C_BGA170  [H5GC4H24AJR-R0C_BGA_170P]  161.51 119.31 90 bottom
UX1  S IC NPCT750JAAYX QFN 32P TPM  [NPCT750JAAYX_QFN32_5X5]  89.58 33.87 180 top
UZ1  -  [EM5209VF_DFN14_3X2]  128.29 107.81 270 bottom
UZ2  S IC EM5201V DFN3X3 8P LOAD SWITCH  [TPS22961DNYR_WSON8]  152.26 39.22 90 top
UZ3  -  [EM5209VF_DFN14_3X2]  37.9 59.23 270 top
UZ4  -  [TPS22967DSGR_SON8_2X2]  69.45 32.74 0 top
UZ5  -  [TPS22967DSGR_SON8_2X2]  135.51 116.91 270 bottom
UZ6  -  [EM5209VF_DFN14_3X2]  120.23 109.55 180 bottom
UZ7  -  [TPS22961DNYR_WSON8]  95.2 62.12 270 top
YC1  24MHZ_12PF_X3G024000DC1H  [Y_X3G024000DC1H_4P]  145.66 48.72 270 bottom
YC2  32.768KHZ_9PF_X1A000141000200  [Y_X1A000141000200_2P]  105.83 44.56 180 top
YE1  32.768KHZ_9PF_X1A000141000200  [Y_X1A000141000200_2P]  30.55 70.76 270 top
YL1  25MHZ_10PF_7V25000014  [Y_7V25000014_4P]  16.14 82.88 270 top
YV1  27MHZ_10PF_7V27000050  [Y_7V27000011_4P]  108.36 142.24 270 bottom

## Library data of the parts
C1 C2 C4-C7 C9 C12-C15 C17-C19 C21-C26 C28 C30-C33 C36 CA1 CA3 CA5 CA7-CA16 CA19-CA22 CA28-CA31 CA35-CA40 CC1-CC5 CC11-CC13 CC20-CC25 CC35-CC40 CC45-CC48 CC51 CC53 CC56 CC67-CC71 CC74-CC79 CD19-CD23 CD25 CD27 CD32-CD34 CD43-CD52 CE1-CE28 CE30-CE32 CI1-CI9 CL6 CL10-CL15 CL17 CL18 CL21 CO1 CO2 CO4-CO7 CS3 CS4 CS7-CS18 CS29 CS30 CS32 CT2-CT11 CT15-CT18 CT20 CU1 CU2 CU4 CU9 CU14 CU15 CV17 CV18 CV27-CV32 CV40-CV45 CV47 CV49 CV54 CV61 CV67-CV78 CV81 CV82 CV84 CV86 CV87 CV91 CV96-CV109 CV152 CV173 CW1-CW6 CX1-CX7 CZ3-CZ8 CZ11 CZ12 CZ15-CZ18 CZ20 CZ22 CZ23 CZ25-CZ28 CZ30 CZ32-CZ37 CZ40 EC1 EC2 PC5 PC6 PC11-PC15 PC315 PC317 PC501 PC502 PC505-PC508 PC515-PC517 PC1805-PC1807 PC2503-PC2506 PCA03 PCA04 PCA05 PCA06 PCA07 PCA08 PCB01 PCB02 PCB03 PCB04 PCB05 PCB06 PCB07 PCB08 PCB09-PCB19 PCB24-PCB28 PCB35 PCB36 PCB71 PCG05 PCG06 PCG07 PCG08 PCG09-PCG11 PCH01 PCH02 PCH09-PCH12 PCH14-PCH16 PCI05 PCI06 PCI07 PCI08 PCI09-PCI11 PCI21 PCI22 PCI27-PCI31 PCM01 PCM02 PCM11-PCM19 PCM22 PCM23 PCV04 PCV05 PCV06 PCV07 PCV08 PCV10 PCV16-PCV23 PCV25-PCV34 PCW01 PCW02 PCW09-PCW12 PCW14-PCW16 PCZ01 PCZ02 PCZ03 PCZ04 PCZ05 PCZ06 PCZ07 PCZ08 PCZ09-PCZ33 PCZ35 PCZ36 = C_0402
C3 C8 C16 C35 C37 C39 CC6-CC8 CC10 CC14-CC16 CC19 CC28-CC33 CC41-CC44 CC50 CC52 CC55 CC59-CC66 CD26 CD28 CD30 CD31 CD35-CD42 CL16 CL19 CU13 CU16 CV1 CV9-CV16 CV20 CV33 CV34 CV46 CV50 CV55-CV60 CV62-CV65 CV83 CV85 CV88-CV90 CV92-CV95 CV120 CV121 CV150 CV151 CV153-CV172 CV174-CV191 CZ1 CZ2 CZ9 CZ10 CZ13 CZ14 CZ19 CZ21 CZ24 CZ29 CZ31 CZ38 CZ39 CZ41 PCA110-PCA115 PCG121-PCG131 PCG135 PCI134-PCI140 PCI151-PCI185 = C_0201
C27 C29 CA2 CA4 CA6 CA17 CA18 CA33 CA34 CC34 CC49 CC54 CC72 CO3 CS1 CS5 CS31 CS33 CT1 CT12-CT14 CU5 CU6 CU10 CU11 CU17 PC312-PC314 PC316 PC503 PC504 PC509-PC514 PC519-PC521 PC1801-PC1804 PC2501 PC2502 PCA01 PCA02 PCA09 PCA101-PCA109 PCA117 PCA118 PCB20-PCB23 PCB29-PCB34 PCC01 PCC02 PCC03 PCC04 PCG01 PCG02 PCG03 PCG04 PCG12 PCG101-PCG120 PCG132-PCG134 PCH03 PCH04 PCH05 PCH06 PCH07 PCH08 PCH13 PCI01 PCI02 PCI03 PCI04 PCI12 PCI23-PCI26 PCI32 PCI101-PCI110 PCI113-PCI130 PCM03 PCM04 PCM05 PCM06 PCM07 PCM08 PCM09 PCM10 PCM20 PCV01 PCV02 PCV03 PCV09 PCV11-PCV15 PCV24 PCV35 PCV36 PCW03 PCW04 PCW05 PCW06 PCW07 PCW08 PCW13 PCW17-PCW20 PCZ34 = C_0603
CA23-CA25 CA32 = C_0402: room: AUDIO
CC9 CC17 CC18 CC26 CC27 = C_0201: room: CPU
CC57 = C_0603: room: CPU
CC58 = C_0402: room: CPU
CD1 CD3 CD4 CD8-CD15 = C_0201: room: DDR4
CD2 CD5-CD7 CD16-CD18 CD29 = C_0402: room: DDR4
CD24 PCG171 PCG172 PCI186-PCI189 PCV171 PCV172 = C_D2
CL1-CL5 CL7-CL9 = C_0402: room: LAN
CL20 = C_1206
CLRP1 CLRP2 = SHORTPADS: User Part Number: PART#
CU7 CU12 = C_A
CV2-CV8 CV26 = C_0201: room: GPU
D1 = BAS40C_SOT23-3
D2 D4 DA3 = BAT54C_SOT23-3
D3 D5 = RB551V-30_SOD323-2
D8 DW1 DW2 DZ2 DZ7 = RB520SM-30T2R_EMD2-2
DA1 DA2 DA6 DA7 ED1 = L03ESDL5V0CC3-2_SOT23-3
DA4 = BAT54ATB_SOT523-3
DA5 = AZ5123-02SPR7G_SOT23-3
DE1 = AZ5125-01HPR7G_SOD523-2
DI1 = BAW56W_SOT323-3
DZ1 DZ4-DZ6 = RB751S40T1G_SOD523-2
ED2-ED4 EU5 EU6 = L03ESDL5V0CG3-2_SOT-523-3
EU1 EU3 EU8 EU9 = L05ESDL5V0NA-4_SLP2510P8-10-9
EU2 EU4 EU10 EU11 = AZC199-02SPR7G_SOT23-3
EU7 = L30ESD24VC3-2_SOT23-3
F1 = F_SMD1812P150TF-24
F3 = F_MF-NSMF050-2
FD1-FD4 = FIDUCIAL_C40M80: room: ETY-ROOM
FI1 = F_1206L150PR
H1 H5-H7 = H_3P0-G: room: SCREW
H3 = H_5P0: room: SCREW
H4 = H_3P0: room: SCREW
H8 = H_3P3-G
H9 H10 = H_3P5
H11 H12 = H_3P2-G
H13 = H_3P0X4P0
H14 = H_5P6N
HCPU1-HCPU4 = H_3P9
JDB1 = HRS_BM20B-20DS-0P4V_20P-T
JDEG1 JESPI1 = JXT_FP241AH-010GAAM_10P
JDIMM1 = LOTES_ADDR0206-P001A02_260P: room: DDR4
JDIMM2 = LOTES_ADDR0205-P001A02_260P: room: DDR4
JEDP1 = ACES_51540-04001-P01_40P
JFAN1 JSPK1 = ACES_50224-00401-001_4P
JFP1 = ACES_51522-00801-001_8P
JHDD1 = ACES_51625-01201-001_12P
JHDMI1 = ACON_HMRF6-AK120C_19P-T
JHP1 = YUQIU_PJ753-F07J1BE-B_7P-T
JIOB1 = ACES_51524-0160N-001_16P
JKB1 = HEFEN_AFB02-S30F1A-HF_30P-T
JKBBL1 = ACES_51575-00401-001_4P
JLAN1 = SINGA_2RJ3076-078211F_8P-T
JODD1 = ACES_50673-0120N-P01_12P
JP1 = JUMP_43X39: room: USB
JP2 JP5 PJP301 PJP1801 PJP2501 PJP2502 PJPA01 PJPH01 PJPM01 PJPM03 PJPW01 = JUMP_43X39
JP3 JP8-JP11 PJP2 PJP501-PJP503 PJP1802 = JUMP_43X79
JPWR1 = JXT_FP226H-004S1AM_4P
JSSD1 = LCN_DAN05-67306-0103_75P
JTP1 = ACES_51524-0080N-001_8P
JUSB1 JUSB2 = ACON_TARAN-9R1391_9P
JUSBC1 = JAE_DX07S024JJ2R1300_24P
JVGA1 = ACES_51625-01601-001_16P-T
JWLAN1 = LOTES_APCI0136-P001A_75P
L3 LT1 LU1 LU4 LU7 LU8 = INPAQ_MCM1012B900F06BP_4P
L4 = INPAQ_MCM1012B900F06BP_4P-NPM
LA1-LA4 = MURAT_BLM15PX330SN1D_2P
LA5 = MURAT_BLM15PX221SN1D_2P
LED1 = LED_LTW-295DSKS-5A_4P
LI1-LI4 LU2 LU3 LU5 LU6 = INPAQ_HCM1012GH900BP_4P-NPM
LV2 LV7 LV8 PHV01 PHV02 PHZ01 PHZ02 PHZ03 PHZ04 PHZ05 PR1 PR7 PR31 PR33-PR45 PR302-PR304 PR306-PR308 PR504 PR506 PR508-PR511 PR1801-PR1803 PR1805 PR1807 PR2501-PR2505 PRB03 PRB04 PRB07 PRB08 PRB09-PRB13 PRB16-PRB18 PRB21 PRB23-PRB28 PRB30 PRB31 PRB34-PRB36 PRB38 PRB39 PRB42-PRB45 PRG02 PRH01 PRH02 PRH04 PRH05 PRH06 PRH08 PRH09 PRH11 PRH12 PRI02 PRI22 PRM03 PRM06 PRM07 PRM08 PRM09-PRM11 PRV02 PRV03 PRV04 PRV05 PRV08 PRV09 PRV10 PRV12 PRV14 PRV16-PRV19 PRV22 PRV25-PRV33 PRV35 PRW01 PRW02 PRW03 PRW04 PRW05 PRW06 PRW09-PRW11 PRW13 PRZ01 PRZ04 PRZ05 PRZ06 PRZ08 PRZ10 PRZ11 PRZ15 PRZ16 PRZ19-PRZ21 PRZ23 PRZ24 PRZ26-PRZ28 PRZ30-PRZ33 PRZ35-PRZ43 PRZ45 PRZ46 PRZ48-PRZ52 PRZ55-PRZ58 PRZ60 PRZ61 PRZ64-PRZ69 R1 R2 R6 R14 R15 R17-R19 R25-R28 R30 R31 R34-R43 R45-R50 R52 R54 R55 R57-R65 R72 R75-R80 R83 R86-R92 RA4 RA7-RA9 RA11 RA15-RA18 RA23-RA28 RA31-RA34 RC1-RC3 RC8 RC10 RC11 RC13 RC15 RC16 RC24 RC26 RC28 RC29 RC31-RC43 RC49 RC51 RC55 RC62-RC66 RC70 RC71 RC73 RC77 RC81-RC83 RC85-RC87 RC89 RC93 RC94 RC97-RC100 RC103-RC127 RC133-RC146 RC149-RC158 RC160 RC162 RC164 RC165 RC167-RC170 RC174 RC175 RC177-RC183 RC187-RC209 RD8 RD10-RD14 RD21-RD24 RE1-RE4 RE8-RE12 RE16-RE28 RE30-RE32 RE35 RE36 RE38-RE40 RE42 RE45-RE52 RE57 RE58 RE60 RE90-RE95 RH1 RI1-RI24 RL2 RL3 RL6 RL7 RL9-RL11 RO1 RS1 RS30 RS31 RT2-RT4 RT6-RT20 RT23 RU3-RU6 RU9-RU12 RV1-RV3 RV5 RV6 RV8 RV9 RV11-RV19 RV22 RV25 RV26 RV29 RV32-RV45 RV48-RV51 RV53-RV55 RV59 RV78-RV82 RV85-RV89 RV117 RV119 RV121 RV123 RV134 RV135 RV151-RV153 RV155-RV159 RV162 RV163 RV165 RV166 RW3-RW7 RX1 RX5 RX6 RX9 RX11-RX22 RZ1 RZ3-RZ7 RZ10-RZ12 = R_0402
LV6 = MURAT_BLM15BB221SN1D_2P
PBATT1 = ACES_50458-01001-P01_10P-T
PC1-PC4 = C_0402: room: DCIN
PC301 = C_0402: room: ETY-ROOM
PC302 PC305-PC308 = C_0402: room: 3_5V
PC303 PC304 PC309 = C_0603: room: 3_5V
PC310 PC311 = C_0603: room: ETY-ROOM
PCB70 = C_B2
PCG13 PCI13 = C_EEFCX1E330R
PCI14 = C_6P3X4P5-NPM
PD1 PD5 PD6 = TVNST52302AB0_SOT523-3
PD2 PD3 = BAV99W_SC70-3
PD14 PDB13 = PJSOT24C_SOT23-3
PD501 PDM01 = RB751V-40_SOD323-2
PDB01 = LRB715FT1G_SOT323-3
PJP1 PJP3 PJPG01 PJPI01 PJPV01 = JUMP_43X79-NPM
PJP302 PJPH02 PJPM02 PJPW02 = JUMP_43X118
PJPB01 = JUMP_43X118-NPM
PJPDC1 = ACES_50458-00601-001_6P-T
PL1 = 5A_Z150_1210_2P: room: DCIN
PL2 = 5A_Z150_1210_2P-NPM: room: DCIN
PL3 = MURAT_BLM15AG102SN1D_2P
PL4 = 5A_Z150_1210_2P: room: BATT
PL301 PL501 PLB01 PLH01 PLM01 = L_7X7X3_M_2P
PL311 PL1811 PLH11 PLM11 PLW11 = TAI-T_HCB2012KF-121T50_2P-NPM
PL511 = 5A_Z150_1210_2P-NPM
PL1801 PLW01 = L_5X5X3_M_2P
PLA01 = L_5X5X3_M
PLB02 = 5A_Z80_0805_2P
PLG01 PLI01 PLI02 PLV01 PLV02 = L_7X7X4_M
PLG11 PLI11 PLV11 = 5A_Z150_1210_2P
PQ1 = FDV301N-G_SOT23-3
PQ2 = MMST3904-7-F_SOT323-3
PQ11 PQB30 PQB31 QI2 = DMN65D8LW-7_SOT323-3
PQ12 PQ13 = DMN65D8LDW-7_SOT363-6
PQA01 PQM01 = AONH36334_DFN3X3A8-10
PQB11-PQB13 = EMB04N03H_EDFN5X6-8-5
PQB25 PQB26 = AON7702L_DFN8-5
PQB28 = LMUN5113T1G_SOT323-3
PQB29 = LTC015EUBFS8TL_UMT3F
PQB32 PQB33 = RUM002N02GT2L_VMT3
PQV01 PQV02 PQV03 PQV04 = AON6994_DFN5X6D-8-7
PR3 PR5 PR6 = R_0402: room: BATT
PR4 = R_0402: room: ETY-ROOM
PR32 PR305 PR505 PR1804 PRA02 PRB40 PRG03 PRH07 PRI03 PRI23 PRM01 PRV06 PRV23 PRW07 RS32 = R_1206
PR301 PR501 PRB14 PRV01 PRV21 RA3 RC128 RE5 RE6 RE44 RV7 RV10 RV23 RV27 RV30 RV31 = R0603_0OHM
PR502 PR503 PR507 PRB06 PRB19 PRB20 PRB22 PRB29 PRB32 PRB33 PRB37 PRH03 PRV15 PRV20 PRV34 PRV36 PRV37 PRZ03 PRZ07 PRZ14 PRZ18 PRZ22 PRZ34 PRZ47 PRZ53 PRZ59 PRZ63 R5 R53 RA2 RA5 RA6 RC131 RC132 RE43 RX10 = R0402_0OHM
PRA01 PRB41 PRG01 PRI01 PRI21 PRM02 PRM04 PRM05 PRV07 PRV13 PRV24 PRZ13 PRZ25 PRZ29 PRZ44 R8 R67 R81 R82 R95 RC129 RC130 RE7 RL12-RL15 RS3 RT1 RV24 RW1 RW2 = R_0603
PRA03 PRG04 PRI24 PRM12 = R_1206_4P-D-NPM
PRB01 PRB02 = R_1206_4P-D
PRB15 PRC02 PRC04 PRC06 PRC08 PRC10 = R_0805
PRC01 PRC03 PRC05 PRC07 PRC09 = SOLDER_PREFORMS_0603-NPM
PU301 = SY8286BRAC_QFN20_3X3
PU501 = SY8288CRAC_QFN20_3X3
PU1801 = RT8061AZQW_WDFN10_3X3
PU2501 = RT9059GSP_SO8
PUA01 = NCP81253MNTBG_DFN8_2X2
PUB01 = ISL95522HRZ-T_TQFN32_4X4
PUG01 PUI01 PUI02 = NCP302045MNTXG_PQFN33_5X5
PUH01 = RT6228AGQUF_UQFN12_3X3
PUM01 = RT8207PGQW_WQFN20_3X3
PUV01 = ISL62771HRTZ-T_TQFN40_5X5
PUW01 = RT6226AGQUF_UQFN12_3X3
PUZ01 = NCP81218MNTXG_QFN48_6X6
Q1 Q5 Q6 QI1 = 2N7002K_SOT23-3
Q2 Q4 Q12 = DDTA144VCA-7-F_SOT23-3
Q3 Q7-Q9 QA1 = LN2306LT1G_SOT23-3
Q10 Q11 Q15 Q16 QC1 QI3 QS1 QT1 = DMN66D0LDW-7_SOT363-6
Q13 = LMBT3904LT1G_SOT23-3
Q17 = LP2301ALT1G_SOT23-3
Q18 = L2N7002WT1G_SC-70-3
QV1 = 2N7002KDWH_SOT363-6
R10 R12 RT21 RT22 RU1 RU2 RU7 RU8 RU13-RU16 = R_0402-NPM
R11 R84 R85 R96 RB1-RB12 RC79 RC84 RC171-RC173 RD15 RD18 RD19 RE65-RE89 RL16 RS2 RS28 RS29 RS33 RT5 RW10 RZ2 RZ9 = R_0201
R13 RA35 RC101 RC102 RC147 RC148 RD7 RD9 RD16 RD17 RD20 RE29 RE34 RE41 RE53-RE55 RS34 RW8 RZ8 = R0201_0OHM
RA1 = R0805_0OHM
RA10 RA12-RA14 RA29 RA30 = R_0402: room: AUDIO
RA19-RA22 = MURAT_BLM15PD600SN1D_2P
RC4-RC7 RC9 RC12 RC17-RC23 RC25 RC27 RC44-RC48 RC50 RC52-RC54 RC56-RC59 RC61 RC68 RC69 RC72 RC74-RC76 RC78 RC90-RC92 RC95 RC96 = R_0402: room: CPU
RC14 RC60 RC80 = R_0201: room: CPU
RC30 = R0603_0OHM: room: CPU
RC88 = R_0402: room: RTC
RD1 = R_0402: room: DDR4
RD2 RD4 RD6 = R_0201: room: DDR4
RD3 RD5 = R0201_0OHM: room: DDR4
RL1 = R_0603: room: LAN
RL4 = R0603_0OHM: room: LAN
RL5 = R0201_0OHM: room: LAN
RL8 = R_0402: room: LAN
RP34 = RP_0804_8P4R
RV4 RV20 RV21 RV52 RV83 RV84 = R_0402: room: GPU
SW1 = SW_TST71-N-220-T170-S017_2P
TL1 TL2 = BOTH_NS0014-LF_16P
TP1-TP12 TP14-TP32 TP34 TP46-TP49 TP51-TP81 TPC1-TPC24 = TPC12
U1 U2 UL2 = SY6288C20AAC_SOT23-5
U3 = NCT7718W_MSOP8
UA1 = ALC3204-CG_MQFN40_5X5: room: AUDIO
UC1 = WHL-U42_BGA_1528P-T: room: CPU
UC2 = 74AUP1G07GW_TSSOP5: room: CPU
UC3 UC11 = W25Q128FVSIQ_SO8
UC4 UC5 UC9 UV2 UV3 = SN74AHC1G08DCKR_SC70-5
UC6 UC8 = 74AUP1G07GW_TSSOP5
UE1 = MEC1416-NU-D0_VTQFP128_14X14
UE2 = NL17SZ06DFT2G_SC70-5
UL1 = RTL8106E-CG_QFN32_4X4-S: room: LAN
US2 = LNG2DMTR_LGA12_2X2
UT1 = TPS25810RVCR_QFN20_4X3-S
UT2 = TUSB542RWQR_X2QFN18_2X2P4
UU1 UU2 = SY6288D20AAC_SOT23-5
UV1 = 216-0842024-A11-MAR_FCBGA_631P: room: GPU
UV13 UV15 = H5GC4H24AJR-R0C_BGA_170P
UX1 = NPCT750JAAYX_QFN32_5X5
UZ1 UZ3 UZ6 = EM5209VF_DFN14_3X2
UZ2 UZ7 = TPS22961DNYR_WSON8
UZ4 UZ5 = TPS22967DSGR_SON8_2X2
YC1 = Y_X3G024000DC1H_4P: room: CPU
YC2 = Y_X1A000141000200_2P: room: CPU
YE1 = Y_X1A000141000200_2P
YL1 = Y_7V25000014_4P: room: LAN
YV1 = Y_7V27000011_4P: room: GPU

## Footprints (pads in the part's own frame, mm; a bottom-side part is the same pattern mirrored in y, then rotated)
2N7002K_SOT23-3
  oval 1.016x1.524 smd: 1(0,0) 2(0.965,2.083) 3(-0.965,2.083)
2N7002KDWH_SOT363-6
  oval 0.356x0.889 smd: 1(0,0) 2(0.65,0) 3(1.3,0) 4(1.3,1.6) 5(0.65,1.6) 6(0,1.6)
5A_Z80_0805_2P
  rect 0.813x1.397 smd: 1(0,0) 2(1.702,0)
5A_Z150_1210_2P
  rect 0.991x2.997 smd: 1(0,0) 2(2.7,0)
5A_Z150_1210_2P-NPM
  rect 0.991x2.997 smd: 1(0,0) 2(2.7,0)
74AUP1G07GW_TSSOP5
  oval 0.381x1.346 smd: 1(0,0) 2(0.65,0) 3(1.3,0) 4(1.3,1.79) 5(0,1.79)
216-0842024-A11-MAR_FCBGA_631P
  round 0.406 smd: A3(0.8,0) A30(20.8,0) A32(21.6,0) AB7(3.2,-15) AB8(4,-15) AB9(4.8,-15) AB10(5.6,-15) AB23(16,-15) AB24(16.8,-15) AB25(17.6,-15) AB26(18.4,-15) AC11(6.6,-16) AC13(7.8,-16) AC14(9,-16) AC16(10.2,-16) AC17(11.4,-16) AC19(12.6,-16) AC20(13.8,-16) AC22(15,-16) AD11(6.6,-16.8) AD13(7.8,-16.8) AD14(9,-16.8) AD16(10.2,-16.8) AD17(11.4,-16.8) AD19(12.6,-16.8) AD20(13.8,-16.8) AD22(15,-16.8) AE11(6.6,-17.6) AE13(7.8,-17.6) AE14(9,-17.6) AE16(10.2,-17.6) AE17(11.4,-17.6) AE19(12.6,-17.6) AE20(13.8,-17.6) AE22(15,-17.6) AF11(6.6,-18.4) AF13(7.8,-18.4) AF14(9,-18.4) AF16(10.2,-18.4) AF17(11.4,-18.4) AF19(12.6,-18.4) AF20(13.8,-18.4) AF22(15,-18.4) AK1(0,-20.8) AK3(0.8,-20.8) AK30(20.8,-20.8) AK32(21.6,-20.8) AM1(0,-21.6) AM3(0.8,-21.6) AM30(20.8,-21.6) AM32(21.6,-21.6) C1(0,-0.8) C3(0.8,-0.8) C30(20.8,-0.8) C32(21.6,-0.8) G11(6.6,-3.2) G13(7.8,-3.2) G14(9,-3.2) G16(10.2,-3.2) G17(11.4,-3.2) G19(12.6,-3.2) G20(13.8,-3.2) G22(15,-3.2) H11(6.6,-4) H13(7.8,-4) H14(9,-4) H16(10.2,-4) H17(11.4,-4) H19(12.6,-4) H20(13.8,-4) H22(15,-4) J11(6.6,-4.8) J13(7.8,-4.8) J14(9,-4.8) J16(10.2,-4.8) J17(11.4,-4.8) J19(12.6,-4.8) J20(13.8,-4.8) J22(15,-4.8) K11(6.6,-5.6) K13(7.8,-5.6) K14(9,-5.6) K16(10.2,-5.6) K17(11.4,-5.6) K19(12.6,-5.6) K20(13.8,-5.6) K22(15,-5.6) L7(3.2,-6.6) L8(4,-6.6) L9(4.8,-6.6) L10(5.6,-6.6) L23(16,-6.6) L24(16.8,-6.6) L25(17.6,-6.6) L26(18.4,-6.6) N7(3.2,-7.8) N8(4,-7.8) N9(4.8,-7.8) N10(5.6,-7.8) N23(16,-7.8) N24(16.8,-7.8) N25(17.6,-7.8) N26(18.4,-7.8) P7(3.2,-9) P8(4,-9) P9(4.8,-9) P10(5.6,-9) P23(16,-9) P24(16.8,-9) P25(17.6,-9) P26(18.4,-9) T7(3.2,-10.2) T8(4,-10.2) T9(4.8,-10.2) T10(5.6,-10.2) T23(16,-10.2) T24(16.8,-10.2) T25(17.6,-10.2) T26(18.4,-10.2) U7(3.2,-11.4) U8(4,-11.4) U9(4.8,-11.4) U10(5.6,-11.4) U23(16,-11.4) U24(16.8,-11.4) U25(17.6,-11.4) U26(18.4,-11.4) W7(3.2,-12.6) W8(4,-12.6) W9(4.8,-12.6) W10(5.6,-12.6) W23(16,-12.6) W24(16.8,-12.6) W25(17.6,-12.6) W26(18.4,-12.6) Y7(3.2,-13.8) Y8(4,-13.8) Y9(4.8,-13.8) Y10(5.6,-13.8) Y23(16,-13.8) Y24(16.8,-13.8) Y25(17.6,-13.8) Y26(18.4,-13.8)
  round 0.305 smd: A5(1.6,0) A7(3.2,0) A9(4.8,0) A11(6.4,0) A13(8,0) A15(9.6,0) A17(11.2,0) A19(12.8,0) A21(14.4,0) A23(16,0) A25(17.6,0) A27(19.2,0) A28(20,0) AA1(0,-14.4) AA3(0.8,-14.4) AA5(1.6,-14.4) AA6(2.4,-14.4) AA27(19.2,-14.4) AA29(20.4,-14.4) AA31(21.2,-14.4) AB2(0.4,-15.2) AB4(1.2,-15.2) AB6(2.4,-15.2) AB27(19.2,-15.2) AB28(20,-15.2) AB30(20.8,-15.2) AB32(21.6,-15.2) AC1(0,-16) AC3(0.8,-16) AC5(1.6,-16) AC6(2.4,-16) AC7(3.2,-16) AC8(4,-16) AC9(4.8,-16) AC10(5.6,-16) AC23(16,-16) AC24(16.8,-16) AC25(17.6,-16) AC26(18.4,-16) AC27(19.2,-16) AC29(20.4,-16) AC31(21.2,-16) AD2(0.4,-16.8) AD4(1.2,-16.8) AD6(2.4,-16.8) AD7(3.2,-16.8) AD8(4,-16.8) AD9(4.8,-16.8) AD10(5.6,-16.8) AD23(16,-16.8) AD24(16.8,-16.8) AD25(17.6,-16.8) AD26(18.4,-16.8) AD27(19.2,-16.8) AD28(20,-16.8) AD30(20.8,-16.8) AD32(21.6,-16.8) AE1(0,-17.6) AE3(0.8,-17.6) AE5(1.6,-17.6) AE6(2.4,-17.6) AE7(3.2,-17.6) AE8(4,-17.6) AE9(4.8,-17.6) AE10(5.6,-17.6) AE23(16,-17.6) AE24(16.8,-17.6) AE25(17.6,-17.6) AE26(18.4,-17.6) AE27(19.2,-17.6) AE29(20.4,-17.6) AE31(21.2,-17.6) AF2(0.4,-18.4) AF4(1.2,-18.4) AF6(2.4,-18.4) AF7(3.2,-18.4) AF8(4,-18.4) AF9(4.8,-18.4) AF10(5.6,-18.4) AF23(16,-18.4) AF24(16.8,-18.4) AF25(17.6,-18.4) AF26(18.4,-18.4) AF27(19.2,-18.4) AF28(20,-18.4) AF30(20.8,-18.4) AF32(21.6,-18.4) AG1(0,-19.2) AG3(0.8,-19.2) AG5(1.6,-19.2) AG6(2.4,-19.2) AG7(3.2,-19.2) AG8(4,-19.2) AG9(4.8,-19.2) AG10(5.6,-19.2) AG11(6.4,-19.2) AG12(7.2,-19.2) AG13(8,-19.2) AG14(8.8,-19.2) AG15(9.6,-19.2) AG16(10.4,-19.2) AG17(11.2,-19.2) AG18(12,-19.2) AG19(12.8,-19.2) AG20(13.6,-19.2) AG21(14.4,-19.2) AG22(15.2,-19.2) AG23(16,-19.2) AG24(16.8,-19.2) AG25(17.6,-19.2) AG26(18.4,-19.2) AG27(19.2,-19.2) AG29(20.4,-19.2) AG31(21.2,-19.2) AH1(0,-20) AH3(0.8,-20) AH5(1.6,-20) AH6(2.4,-20) AH8(4,-20) AH10(5.6,-20) AH12(7.2,-20) AH14(8.8,-20) AH16(10.4,-20) AH18(12,-20) AH20(13.6,-20) AH22(15.2,-20) AH24(16.8,-20) AH26(18.4,-20) AH28(20,-20) AH30(20.8,-20) AH32(21.6,-20) AJ7(3.2,-20.4) AJ9(4.8,-20.4) AJ11(6.4,-20.4) AJ13(8,-20.4) AJ15(9.6,-20.4) AJ17(11.2,-20.4) AJ19(12.8,-20.4) AJ21(14.4,-20.4) AJ23(16,-20.4) AJ25(17.6,-20.4) AJ27(19.2,-20.4) AK5(1.6,-20.8) AK6(2.4,-20.8) AK8(4,-20.8) AK10(5.6,-20.8) AK12(7.2,-20.8) AK14(8.8,-20.8) AK16(10.4,-20.8) AK18(12,-20.8) AK20(13.6,-20.8) AK22(15.2,-20.8) AK24(16.8,-20.8) AK26(18.4,-20.8) AK28(20,-20.8) AL7(3.2,-21.2) AL9(4.8,-21.2) AL11(6.4,-21.2) AL13(8,-21.2) AL15(9.6,-21.2) AL17(11.2,-21.2) AL19(12.8,-21.2) AL21(14.4,-21.2) AL23(16,-21.2) AL25(17.6,-21.2) AL27(19.2,-21.2) AM5(1.6,-21.6) AM6(2.4,-21.6) AM8(4,-21.6) AM10(5.6,-21.6) AM12(7.2,-21.6) AM14(8.8,-21.6) AM16(10.4,-21.6) AM18(12,-21.6) AM20(13.6,-21.6) AM22(15.2,-21.6) AM24(16.8,-21.6) AM26(18.4,-21.6) AM28(20,-21.6) B6(2.4,-0.4) B8(4,-0.4) B10(5.6,-0.4) B12(7.2,-0.4) B14(8.8,-0.4) B16(10.4,-0.4) B18(12,-0.4) B20(13.6,-0.4) B22(15.2,-0.4) B24(16.8,-0.4) B26(18.4,-0.4) C5(1.6,-0.8) C7(3.2,-0.8) C9(4.8,-0.8) C11(6.4,-0.8) C13(8,-0.8) C15(9.6,-0.8) C17(11.2,-0.8) C19(12.8,-0.8) C21(14.4,-0.8) C23(16,-0.8) C25(17.6,-0.8) C27(19.2,-0.8) C28(20,-0.8) D6(2.4,-1.2) D8(4,-1.2) D10(5.6,-1.2) D12(7.2,-1.2) D14(8.8,-1.2) D16(10.4,-1.2) D18(12,-1.2) D20(13.6,-1.2) D22(15.2,-1.2) D24(16.8,-1.2) D26(18.4,-1.2) E1(0,-1.6) E3(0.8,-1.6) E5(1.6,-1.6) E7(3.2,-1.6) E9(4.8,-1.6) E11(6.4,-1.6) E13(8,-1.6) E15(9.6,-1.6) E17(11.2,-1.6) E19(12.8,-1.6) E21(14.4,-1.6) E23(16,-1.6) E25(17.6,-1.6) E27(19.2,-1.6) E28(20,-1.6) E30(20.8,-1.6) E32(21.6,-1.6) F2(0.4,-2.4) F4(1.2,-2.4) F6(2.4,-2.4) F7(3.2,-2.4) F8(4,-2.4) F9(4.8,-2.4) F10(5.6,-2.4) F11(6.4,-2.4) F12(7.2,-2.4) F13(8,-2.4) F14(8.8,-2.4) F15(9.6,-2.4) F16(10.4,-2.4) F17(11.2,-2.4) F18(12,-2.4) F19(12.8,-2.4) F20(13.6,-2.4) F21(14.4,-2.4) F22(15.2,-2.4) F23(16,-2.4) F24(16.8,-2.4) F25(17.6,-2.4) F26(18.4,-2.4) F27(19.2,-2.4) F28(20,-2.4) F30(20.8,-2.4) F32(21.6,-2.4) G1(0,-3.2) G3(0.8,-3.2) G5(1.6,-3.2) G6(2.4,-3.2) G7(3.2,-3.2) G8(4,-3.2) G9(4.8,-3.2) G10(5.6,-3.2) G23(16,-3.2) G24(16.8,-3.2) G25(17.6,-3.2) G26(18.4,-3.2) G27(19.2,-3.2) G29(20.4,-3.2) G31(21.2,-3.2) H2(0.4,-4) H4(1.2,-4) H6(2.4,-4) H7(3.2,-4) H8(4,-4) H9(4.8,-4) H10(5.6,-4) H23(16,-4) H24(16.8,-4) H25(17.6,-4) H26(18.4,-4) H27(19.2,-4) H28(20,-4) H30(20.8,-4) H32(21.6,-4) J1(0,-4.8) J3(0.8,-4.8) J5(1.6,-4.8) J6(2.4,-4.8) J7(3.2,-4.8) J8(4,-4.8) J9(4.8,-4.8) J10(5.6,-4.8) J23(16,-4.8) J24(16.8,-4.8) J25(17.6,-4.8) J26(18.4,-4.8) J27(19.2,-4.8) J29(20.4,-4.8) J31(21.2,-4.8) K2(0.4,-5.6) K4(1.2,-5.6) K6(2.4,-5.6) K7(3.2,-5.6) K8(4,-5.6) K9(4.8,-5.6) K10(5.6,-5.6) K23(16,-5.6) K24(16.8,-5.6) K25(17.6,-5.6) K26(18.4,-5.6) K27(19.2,-5.6) K28(20,-5.6) K30(20.8,-5.6) K32(21.6,-5.6) L1(0,-6.4) L3(0.8,-6.4) L5(1.6,-6.4) L6(2.4,-6.4) L27(19.2,-6.4) L29(20.4,-6.4) L31(21.2,-6.4) M2(0.4,-7.2) M4(1.2,-7.2) M6(2.4,-7.2) M27(19.2,-7.2) M28(20,-7.2) M30(20.8,-7.2) M32(21.6,-7.2) N1(0,-8) N3(0.8,-8) N5(1.6,-8) N6(2.4,-8) N27(19.2,-8) N29(20.4,-8) N31(21.2,-8) P2(0.4,-8.8) P4(1.2,-8.8) P6(2.4,-8.8) P27(19.2,-8.8) P28(20,-8.8) P30(20.8,-8.8) P32(21.6,-8.8) R1(0,-9.6) R3(0.8,-9.6) R5(1.6,-9.6) R6(2.4,-9.6) R27(19.2,-9.6) R29(20.4,-9.6) R31(21.2,-9.6) T2(0.4,-10.4) T4(1.2,-10.4) T6(2.4,-10.4) T27(19.2,-10.4) T28(20,-10.4) T30(20.8,-10.4) T32(21.6,-10.4) U1(0,-11.2) U3(0.8,-11.2) U5(1.6,-11.2) U6(2.4,-11.2) U27(19.2,-11.2) U29(20.4,-11.2) U31(21.2,-11.2) V2(0.4,-12) V4(1.2,-12) V6(2.4,-12) V27(19.2,-12) V28(20,-12) V30(20.8,-12) V32(21.6,-12) W1(0,-12.8) W3(0.8,-12.8) W5(1.6,-12.8) W6(2.4,-12.8) W27(19.2,-12.8) W29(20.4,-12.8) W31(21.2,-12.8) Y2(0.4,-13.6) Y4(1.2,-13.6) Y6(2.4,-13.6) Y27(19.2,-13.6) Y28(20,-13.6) Y30(20.8,-13.6) Y32(21.6,-13.6)
  round 0.508 smd: AA11(6.4,-14.2) AA12(7.4,-14.2) AA13(8.4,-14.2) AA15(9.4,-14.2) AA16(10.4,-14.2) AA17(11.2,-14.2) AA18(12.2,-14.2) AA20(13.2,-14.2) AA21(14.2,-14.2) AA22(15.2,-14.2) AB11(6.4,-15.2) AB12(7.4,-15.2) AB13(8.4,-15.2) AB15(9.4,-15.2) AB16(10.4,-15.2) AB17(11.2,-15.2) AB18(12.2,-15.2) AB20(13.2,-15.2) AB21(14.2,-15.2) AB22(15.2,-15.2) L11(6.4,-6.4) L12(7.4,-6.4) L13(8.4,-6.4) L15(9.4,-6.4) L16(10.4,-6.4) L17(11.2,-6.4) L18(12.2,-6.4) L20(13.2,-6.4) L21(14.2,-6.4) L22(15.2,-6.4) M11(6.4,-7.4) M12(7.4,-7.4) M13(8.4,-7.4) M15(9.4,-7.4) M16(10.4,-7.4) M17(11.2,-7.4) M18(12.2,-7.4) M20(13.2,-7.4) M21(14.2,-7.4) M22(15.2,-7.4) N11(6.4,-8.4) N12(7.4,-8.4) N13(8.4,-8.4) N15(9.4,-8.4) N16(10.4,-8.4) N17(11.2,-8.4) N18(12.2,-8.4) N20(13.2,-8.4) N21(14.2,-8.4) N22(15.2,-8.4) R11(6.4,-9.4) R12(7.4,-9.4) R13(8.4,-9.4) R15(9.4,-9.4) R16(10.4,-9.4) R17(11.2,-9.4) R18(12.2,-9.4) R20(13.2,-9.4) R21(14.2,-9.4) R22(15.2,-9.4) T11(6.4,-10.4) T12(7.4,-10.4) T13(8.4,-10.4) T15(9.4,-10.4) T16(10.4,-10.4) T17(11.2,-10.4) T18(12.2,-10.4) T20(13.2,-10.4) T21(14.2,-10.4) T22(15.2,-10.4) U11(6.4,-11.2) U12(7.4,-11.2) U13(8.4,-11.2) U15(9.4,-11.2) U16(10.4,-11.2) U17(11.2,-11.2) U18(12.2,-11.2) U20(13.2,-11.2) U21(14.2,-11.2) U22(15.2,-11.2) V11(6.4,-12.2) V12(7.4,-12.2) V13(8.4,-12.2) V15(9.4,-12.2) V16(10.4,-12.2) V17(11.2,-12.2) V18(12.2,-12.2) V20(13.2,-12.2) V21(14.2,-12.2) V22(15.2,-12.2) Y11(6.4,-13.2) Y12(7.4,-13.2) Y13(8.4,-13.2) Y15(9.4,-13.2) Y16(10.4,-13.2) Y17(11.2,-13.2) Y18(12.2,-13.2) Y20(13.2,-13.2) Y21(14.2,-13.2) Y22(15.2,-13.2)
